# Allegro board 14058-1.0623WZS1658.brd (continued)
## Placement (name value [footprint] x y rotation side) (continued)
C442  SC1U10V2KX-1DLGP  [C402H22]  74.75 116.37 180 bottom
C443  SC4D7U6D3V3KX-DLGP  [C603H36]  91 117.59 180 bottom
C444  SCD1U16V2KX-3DLGP  [C402H22]  77.69 119.72 270 bottom
C445  SC1U10V2KX-1DLGP  [C402H22]  77.41 117.56 0 bottom
C446  SC4D7U6D3V3KX-DLGP  [C603H36]  84.57 114.01 180 bottom
C447  SC1KP50V2KX-1DLGP  [C402H22]  96.59 88.25 180 bottom
C448  SC1U10V2KX-1DLGP  [C402H22]  87.65 115.76 270 bottom
C449  SC22U6D3V5MX-2DLGP  [C805H54]  67.91 126.91 270 top
C452  SC22U6D3V5MX-2DLGP  [C805H54]  62.43 125.46 180 top
C453  SC4D7U6D3V3KX-DLGP  [C603H36]  80.87 110.51 90 bottom
C454  SC4D7U6D3V3KX-DLGP  [C603H36]  83.3 109.19 270 bottom
C455  SCD1U16V2KX-3DLGP  [C402H22]  75.25 114.95 90 bottom
C456  SC1U25V3KX-1-DLGP  [C603H36]  64.51 128.03 270 top
C458  SC4D7U6D3V3KX-DLGP  [C603H36]  78.78 106.36 270 bottom
C459  SC1U10V2KX-1DLGP  [C402H22]  81.1 106.54 270 bottom
C460  SC47U6D3V5MX-1DL-GP  [C805H54]  77.74 111.49 90 bottom
C461  SC4D7U6D3V3KX-DLGP  [C603H36]  84.12 107.33 90 bottom
C463  SCD1U16V2KX-3DLGP  [C402H22]  90.87 112.61 0 bottom
C464  SC4D7U6D3V3KX-DLGP  [C603H36]  81.45 107.56 90 bottom
C465  SCD1U16V2KX-3DLGP  [C402H22]  73.86 111.42 90 bottom
C466  SC4D7U6D3V3KX-DLGP  [C603H36]  86.26 109.65 90 bottom
C467  SC22U6D3V3MX-1-DL-GP  [C603H40]  92.02 112.99 0 bottom
C468  SC4D7U6D3V3KX-DLGP  [C603H36]  93.29 112.99 180 bottom
C469  SCD1U16V2KX-3DLGP  [C402H22]  89.86 112.61 0 bottom
C471  SC22U6D3V5MX-2DLGP  [C805H54]  77.72 113.52 90 bottom
C472  SC4D7U6D3V3KX-DLGP  [C603H36]  87.22 113.55 90 bottom
C473  SC4D7U6D3V3KX-DLGP  [C603H36]  87.98 112.36 90 bottom
C475  SCD1U16V2KX-3DLGP  [C402H22]  96.59 88.51 0 top
C476  SC4D7U6D3V3KX-DLGP  [C603H36]  72.26 113.07 0 bottom
C477  SC10U25V5KX-DL-GP  [C805H58]  64.59 125.46 180 top
C479  SC4D7U6D3V3KX-DLGP  [C603H36]  85.26 116.17 270 bottom
C481  SC4D7U6D3V3KX-DLGP  [C603H36]  88 114.72 90 bottom
C482  SC4D7U6D3V3KX-DLGP  [C603H36]  77.58 109.47 270 bottom
C484  SCD1U16V2KX-3DLGP  [C402H22]  90.11 110.07 0 bottom
C486  SC1U10V2KX-1DLGP  [C402H22]  78.19 107.72 90 bottom
C487  SC4D7U6D3V3KX-DLGP  [C603H36]  80.89 114.4 90 bottom
C488  SC4D7U6D3V3KX-DLGP  [C603H36]  83.57 111.34 270 bottom
C489  SC10U10V5KX-2DLGP  [C805H50]  27.5 125.54 180 top
C490  SC1U25V3KX-1-DLGP  [C603H36]  25.8 125.74 180 top
C491  SC10U6D3V3MX-DL-GP  [C603H36]  24.5 125.77 180 top
C492  SC4D7U6D3V3KX-DLGP  [C603H36]  87.78 107.31 180 bottom
C494  SCD01U25V2KX-3DLGP  [C402H22]  14.04 79.56 90 bottom
C495  SCD01U25V2KX-3DLGP  [C402H22]  14.04 78.55 90 bottom
C496  SCD01U25V2KX-3DLGP  [C402H22]  14.04 74.54 90 bottom
C497  SCD01U25V2KX-3DLGP  [C402H22]  14.04 73.62 90 bottom
C498  SCD01U25V2KX-3DLGP  [C402H22]  14.93 97.4 90 bottom
C499  SCD01U25V2KX-3DLGP  [C402H22]  14.93 96.38 90 bottom
C500  SCD01U25V2KX-3DLGP  [C402H22]  14.93 93.84 90 bottom
C501  SCD01U25V2KX-3DLGP  [C402H22]  14.93 92.82 90 bottom
C502  SCD1U16V2KX-3DLGP  [C402H22]  75.66 106.17 0 bottom
C503  SCD1U16V2KX-3DLGP  [C402H22]  79.09 105.32 90 bottom
C504  SC1U10V2KX-1DLGP  [C402H22]  48.58 101.59 180 bottom
C505  SC1U10V2KX-1DLGP  [C402H22]  48.58 101.59 0 top
C506  SCD1U16V2KX-3DLGP  [C402H22]  91.89 84.26 0 top
C511  SC15P50V2JN-DL-GP  [C402H22]  91.2 96.13 180 top
C512  SCD1U16V2KX-3DLGP  [C402H22]  146.88 234.56 90 top
C513  SC2D2U10V3KX-1DLGP-U  [C603H36]  147.14 233.41 90 top
C514  SCD1U16V2KX-3DLGP  [C402H22]  136.36 228.98 90 top
C515  SC2D2U10V3KX-1DLGP-U  [C603H36]  139.39 226.55 0 top
C516  SC10U6D3V3MX-DL-GP  [C603H36]  138.12 226.55 0 top
C517  SC10U6D3V3MX-DL-GP  [C603H36]  136.85 226.55 0 top
C518  SC1U10V2KX-1DLGP  [C402H22]  142.94 235.83 180 top
C519  SC1U10V2KX-1DLGP  [C402H22]  148.79 242.43 270 top
C520  SC10U10V5KX-2DLGP  [C805H50]  15.44 133.08 270 bottom
C522  SC10P50V2JN-4DLGP  [C402H22]  16.96 132.45 0 top
C523  SC10P50V2JN-4DLGP  [C402H22]  16.96 134.61 180 top
C524  SCD1U16V2KX-3DLGP  [C402H22]  23.44 18.02 180 top
C526  SCD1U16V2KX-3DLGP  [C402H22]  21.66 15.99 0 top
C528  SCD1U16V2KX-3DLGP  [C402H22]  23.44 20.05 180 top
C836  SCD1U16V2KX-3DLGP  [C402H22]  95.7 117.46 90 top
C837  SC22U6D3V5MX-2DLGP  [C805H54]  104.08 119.75 180 top
C1935  SCD1U16V2KX-3DLGP  [C402H22]  152.19 80.38 0 bottom
C3366  SCD1U16V2KX-3DLGP  [C402H22]  166.06 42.15 270 bottom
C3367  SC10U10V5KX-2DLGP  [C805H50]  141.29 45.07 0 top
C3453  SCD1U16V2KX-3DLGP  [C402H22]  91.26 27.67 180 top
C3454  SCD1U16V2KX-3DLGP  [C402H22]  60.27 21.83 0 bottom
C3457  SCD01U50V2KX-1DLGP  [C402H22]  10.48 16.88 90 top
C6702  SCD1U16V2KX-3DLGP  [C402H22]  36.39 115.56 0 top
C6704  SCD01U25V2KX-3LLGP  [C402H22]  62.05 110.78 0 top
C6705  SCD1U16V2KX-3DLGP  [C402H22]  86.76 107.35 0 bottom
C6706  SC4D7U6D3V3KX-DLGP  [C603H36]  80.89 112.46 90 bottom
C6707  SC4D7U6D3V3KX-DLGP  [C603H36]  70.68 117.84 90 bottom
C6708  SCD1U16V2KX-3DLGP  [C402H22]  91 110.07 0 bottom
C6709  SCD1U16V2KX-3-LL-GP  [C402H22]  87.14 117.56 180 bottom
C6710  SC22U6D3V3MX-1-DL-GP  [C603H40]  92.14 110.2 0 bottom
C6711  SC1U10V2KX-1DLGP  [C402H22]  51.63 97.12 0 top
C6712  SCD1U16V2KX-3DLGP  [C402H22]  53.03 97.65 90 top
C6713  SC1U10V2KX-1DLGP  [C402H22]  76.52 93.51 0 bottom
C6714  SCD1U16V2KX-3DLGP  [C402H22]  77.36 92.92 180 top
C6723  SC1U25V3KX-1-DLGP  [C603H36]  81.48 105.52 270 bottom
C6724  SC1U25V3KX-1-DLGP  [C603H36]  89.86 107.17 270 bottom
C6725  SC1U25V3KX-1-DLGP  [C603H36]  74.75 108.83 270 bottom
C7503  SCD1U10V2KX-4DLGP  [C402H22]  49.47 97.01 270 top
C7504  SCD1U10V2KX-4DLGP  [C402H22]  72.84 77.3 0 top
C7505  SCD1U16V2KX-3DLGP  [C402H22]  72.84 77.3 180 bottom
C7506  SCD1U10V2KX-4DLGP  [C402H22]  49.47 96 270 top
C7507  SCD1U16V2KX-3DLGP  [C402H22]  49.47 96 90 bottom
C7508  SCD1U16V2KX-3DLGP  [C402H22]  49.47 94.86 270 top
C7511  SCD1U10V2KX-4DLGP  [C402H22]  49.47 94.86 90 bottom
C7512  SCD1U16V2KX-3DLGP  [C402H22]  54.93 124.7 180 top
C7516  SCD1U16V2KX-3DLGP  [C402H22]  54.93 124.7 0 bottom
C7521  SCD1U10V2KX-4DLGP  [C402H22]  48.96 115.94 270 top
C7522  SCD1U16V2KX-3DLGP  [C402H22]  48.96 114.92 270 top
C9504  SCD1U16V2KX-3DLGP  [C402H22]  36.65 47.87 90 bottom
C9516  SC4D7U6D3V3KX-DLGP  [C603H36]  33.34 42.53 270 bottom
C9518  SCD1U16V2KX-3DLGP  [C402H22]  30.04 48.37 0 bottom
C9520  SC18P50V2JN-1DLGP  [C402H22]  45.17 23.34 90 top
C9522  SC18P50V2JN-1DLGP  [C402H22]  43.14 23.34 270 top
C11358  SC1U10V2KX-1DLGP  [C402H22]  176.41 48.75 180 top
C11359  SCD1U16V2KX-3DLGP  [C402H22]  177.36 48.75 180 top
C11833  SC1U10V2KX-1DLGP  [C402H22]  148.41 81.32 0 bottom
C11834  SC1U10V2KX-1DLGP  [C402H22]  138.75 75.93 270 bottom
C11835  SC1U10V2KX-1DLGP  [C402H22]  153.87 80 0 bottom
C11836  SC1U10V2KX-1DLGP  [C402H22]  142.69 88.76 0 bottom
C11837  SC1U10V2KX-1DLGP  [C402H22]  127.78 93.84 270 top
C11838  SC1U10V2KX-1DLGP  [C402H22]  167.84 58.03 270 top
C11839  SC1U10V2KX-1DLGP  [C402H22]  135.45 63.36 180 top
C11888  SC22U6D3V5MX-2DLGP  [C805H54]  129.1 96 270 top
C11892  SC47P50V2JN-3GP  [C402H22]  140.82 61.29 0 top
C11895  SCD22U10V2KX-2-GP  [C402H22]  77 132.18 0 top
C11898  SCD22U10V2KX-2-GP  [C402H22]  75.48 130.03 0 top
C11900  SCD22U10V2KX-2-GP  [C402H22]  78.53 130.01 0 top
C11902  SCD22U10V2KX-2-GP  [C402H22]  79.92 132.17 0 top
C11904  SCD22U10V2KX-2-GP  [C402H22]  81.19 130.01 0 top
C11905  SCD22U10V2KX-2-GP  [C402H22]  82.46 132.17 0 top
C11907  SCD22U10V2KX-2-GP  [C402H22]  84.62 130.01 0 top
C11908  SCD22U10V2KX-2-GP  [C402H22]  85 132.17 0 top
C12052  SCD01U16V2KX-3DLGP  [C402H22]  154.63 57.39 90 top
C12055  SCD1U16V2KX-3DLGP  [C402H22]  19.88 161.02 90 top
C12056  SC10U10V5KX-2DLGP  [C805H50]  38.68 148.45 90 top
C12057  SCD1U16V2KX-3DLGP  [C402H22]  39.31 149.97 90 top
C12058  SCD1U50V3KX-DL-GP  [C603H35]  36.82 150.1 90 top
C12059  SCD1U50V3KX-DL-GP  [C603H35]  36.82 151.32 270 top
C12060  SCD1U50V3KX-DL-GP  [C603H35]  40.21 154.58 0 top
C12061  SCD1U16V2KX-3DLGP  [C402H22]  152.6 72 90 bottom
C12063  SCD1U16V2KX-3DLGP  [C402H22]  99.89 54.85 180 top
C12064  SCD1U16V2KX-3DLGP  [C402H22]  104.72 54.22 0 bottom
C12065  SC2200P50V2KX-2DLGP  [C402H22]  98.88 55.87 0 bottom
C12098  SC1U100V6KX-LL-GP  [C1206H71]  25.98 6.06 180 bottom
C12100  SC1U100V6KX-LL-GP  [C1206H71]  28.28 6.05 180 bottom
C12101  SCD1U25V3ZY-1-LL-GP  [C603H36]  5.58 14.49 180 top
C12103  SC1U100V6KX-LL-GP  [C1206H71]  32.86 6.06 180 bottom
C12107  SC1U100V6KX-LL-GP  [C1206H71]  30.58 6.06 180 bottom
C12108  SC1U100V6KX-LL-GP  [C1206H71]  35.15 6.06 180 bottom
C12113  SC4D7U10V3KX-DL-GP  [C603H36]  20.26 48.75 180 bottom
C12114  SCD01U25V2KX-3DLGP  [C402H22]  17.21 52.18 90 bottom
C12118  SCD1U16V2KX-3DLGP  [C402H22]  64.52 32.97 180 top
C12119  SCD1U16V2KX-3DLGP  [C402H22]  63.5 32.96 180 top
C12120  SC1U10V2KX-1DLGP  [C402H22]  53.66 21.45 0 bottom
C12121  SC2D2U10V3KX-1DLGP-U  [C603H36]  66.24 26.4 90 top
C12122  SC1U10V2KX-1DLGP  [C402H22]  59.76 14.08 180 top
C12123  SC1U10V2KX-1DLGP  [C402H22]  55.95 16.88 270 top
C12125  SC47P50V2JN-5DLGP  [C402H22]  37.41 232.27 90 top
C12126  SC47P50V3JN-DLGP  [C603H35]  110.56 71.74 270 top
C12127  SC10U10V5KX-2DLGP  [C805H50]  185.36 52.44 90 top
C12128  SCD1U16V2KX-3DLGP  [C402H22]  64.08 21.83 0 bottom
C12131  SC10U10V5KX-2DLGP  [C805H50]  185.74 148.58 90 bottom
C12138  SCD22U10V2KX-2-GP  [C402H22]  76.37 130.03 0 top
C12139  SCD22U10V2KX-2-GP  [C402H22]  77.89 132.18 0 top
C12140  SCD22U10V2KX-2-GP  [C402H22]  79.41 130.01 0 top
C12141  SCD22U10V2KX-2-GP  [C402H22]  80.81 132.17 0 top
C12142  SCD22U10V2KX-2-GP  [C402H22]  82.08 130.01 0 top
C12143  SCD22U10V2KX-2-GP  [C402H22]  83.35 132.17 0 top
C12144  SCD22U10V2KX-2-GP  [C402H22]  83.73 130.01 0 top
C12145  SCD22U10V2KX-2-GP  [C402H22]  85.89 132.17 0 top
C12148  SCD1U16V2KX-3DLGP  [C402H22]  145.36 175.12 180 bottom
C12149  SC1U10V2KX-1DLGP  [C402H22]  147.26 123.43 180 top
C12150  SC1U10V2KX-1DLGP  [C402H22]  149.93 120.89 0 top
C12151  SC2D2U6D3V2MX-DL-GP  [C402H22]  116.25 69.94 270 top
C12152  SC1U10V2KX-1DLGP  [C402H22]  114.29 68.97 90 top
C12153  SC10U6D3V3MX-DL-GP  [C603H36]  182.19 51.93 270 top
C12154  SCD1U16V2KX-3DLGP  [C402H22]  57.22 31.86 0 bottom
C12155  SCD1U16V2KX-3DLGP  [C402H22]  187.27 146.04 270 bottom
C12156  SC1U10V2KX-1DLGP  [C402H22]  194.52 137.64 0 bottom
C12157  SC4D7U6D3V3KX-DLGP  [C603H36]  190.44 149.34 0 bottom
C12158  SCD1U16V2KX-3DLGP  [C402H22]  191.55 149.17 180 bottom
C12159  SC1U10V2KX-1DLGP  [C402H22]  196.46 144.39 90 bottom
C12160  SCD1U16V2KX-3DLGP  [C402H22]  188.03 148.58 180 bottom
C12161  SC1U10V2KX-1DLGP  [C402H22]  189.01 148.58 180 bottom
C12162  SCD1U16V2KX-3DLGP  [C402H22]  191.46 135.09 270 bottom
C12163  SC4D7U6D3V3KX-DLGP  [C603H36]  191.53 134.07 90 bottom
C12164  SC1KP50V2KX-1DLGP  [C402H22]  142.06 94.47 180 top
C12165  SC1U10V2KX-1DLGP  [C402H22]  24.96 253.35 90 bottom
C12166  SCD1U16V2KX-3DLGP  [C402H22]  24.83 251.76 180 bottom
C12167  SCD1U16V2KX-3DLGP  [C402H22]  173.93 205.47 270 bottom
C12168  SCD1U16V2KX-3DLGP  [C402H22]  161.36 206.74 180 bottom
C12169  SC4D7U6D3V3KX-DLGP  [C603H36]  27.12 32.75 0 bottom
C12170  SCD1U16V2KX-3DLGP  [C402H22]  63.06 9.51 0 top
C12171  SCD1U50V3KX-DL-GP  [C603H35]  41.22 38.34 270 bottom
C12172  SCD1U16V2KX-3DLGP  [C402H22]  29.66 39.36 90 bottom
C12174  SC10U10V5KX-2DLGP  [C805H50]  41.98 27.16 270 bottom
C12175  SCD1U16V2KX-3DLGP  [C402H22]  40.46 19.47 270 top
C12176  SCD1U16V2KX-3DLGP  [C402H22]  40.46 18.58 270 top
C12179  SCD1U16V2KX-3DLGP  [C402H22]  47.19 32.63 270 top
C12180  SCD1U16V2KX-3DLGP  [C402H22]  47.19 33.51 270 top
C12181  SCD1U16V2KX-3DLGP  [C402H22]  47.19 34.4 270 top
C12182  SCD1U16V2KX-3DLGP  [C402H22]  47.19 35.29 270 top
C12183  SCD1U16V2KX-3DLGP  [C402H22]  38.04 27.55 270 bottom
C12184  SCD1U16V2KX-3DLGP  [C402H22]  31.44 30.21 90 bottom
C12185  SC10U6D3V3MX-DL-GP  [C603H36]  47.44 26.78 0 top
C12186  SCD1U16V2KX-3DLGP  [C402H22]  43.38 37.96 0 bottom
C12187  SCD1U16V2KX-3DLGP  [C402H22]  46.3 27.42 0 top
C12188  SCD1U16V2KX-3DLGP  [C402H22]  46.93 40.25 180 top
C12189  SC4D7U6D3V3KX-DLGP  [C603H36]  48.08 40.63 180 top
C12190  SC1U25V3KX-1-DLGP  [C603H36]  44.06 51.6 180 top
C12191  SCD1U16V2KX-3DLGP  [C402H22]  37.66 48.75 270 bottom
C12192  SC1U10V2KX-1DLGP  [C402H22]  42.46 51.73 270 top
C12193  SC1U10V2KX-1DLGP  [C402H22]  40.1 51.29 180 top
C12194  SCD1U16V2KX-3DLGP  [C402H22]  31.06 48.37 0 bottom
C12195  SCD1U16V2KX-3DLGP  [C402H22]  32.07 48.37 0 bottom
C12196  SCD1U16V2KX-3DLGP  [C402H22]  29.41 43.17 0 bottom
C12197  SCD1U16V2KX-3DLGP  [C402H22]  29.03 37.83 0 bottom
C12199  SCD1U16V2KX-3DLGP  [C402H22]  151.45 33.9 270 bottom
C12200  SCD1U16V2KX-3DLGP  [C402H22]  167.2 46.47 90 top
C12201  SCD01U50V2KX-1DLGP  [C402H22]  153.71 51.68 180 top
C12202  SCD1U16V2KX-3DLGP  [C402H22]  155.01 43.29 270 top
C12203  SCD01U50V2KX-1DLGP  [C402H22]  155.01 42.4 270 top
C12204  SCD1U16V2KX-3DLGP  [C402H22]  166.06 43.04 270 bottom
C12205  SCD01U50V2KX-1DLGP  [C402H22]  149.04 49.52 180 top
C12206  SCD1U16V2KX-3DLGP  [C402H22]  165.68 47.48 0 bottom
C12207  SCD01U50V2KX-1DLGP  [C402H22]  155.52 46.6 180 bottom
C12208  SCD1U10V2KX-4DLGP  [C402H22]  159.45 51.68 0 top
C12209  SCD1U10V2KX-4DLGP  [C402H22]  158.57 51.68 0 top
C12210  SCD1U10V2KX-4DLGP  [C402H22]  163.26 51.68 0 top
C12211  SCD1U10V2KX-4DLGP  [C402H22]  162.38 51.68 0 top
C12212  SCD1U10V2KX-4DLGP  [C402H22]  167.07 51.68 0 top
C12213  SCD1U10V2KX-4DLGP  [C402H22]  166.19 51.68 0 top
C12214  SCD1U10V2KX-4DLGP  [C402H22]  155.52 51.68 0 top
C12215  SCD1U10V2KX-4DLGP  [C402H22]  154.63 51.68 0 top
C12216  SCD1U16V2ZY-2DLGP  [C402H22]  142.31 15.99 180 top
C12217  SCD1U16V2ZY-2DLGP  [C402H22]  155.16 20.94 0 top
C12218  SC33P50V2JN-3DLGP  [C402H22]  148.15 23.74 0 top
C12219  SC33P50V2JN-3DLGP  [C402H22]  148.15 25.77 180 top
C12220  SCD1U16V2KX-3DLGP  [C402H22]  25.22 53.71 270 bottom
C12221  SCD1U16V2KX-3DLGP  [C402H22]  25.22 54.72 270 bottom
C12222  SCD1U16V2KX-3DLGP  [C402H22]  24.96 52.82 270 bottom
C12223  SCD1U16V2KX-3DLGP  [C402H22]  25.49 54.72 90 top
C12224  SC10U25V5KX-DL-GP  [C805H58]  7.33 6.13 270 top
C12225  SC10U25V5KX-DL-GP  [C805H58]  7.33 8.37 270 top
C12226  SCD1U16V2KX-3DLGP  [C402H22]  10.1 17.94 90 top
C12227  SCD01U50V2KX-1DLGP  [C402H22]  8.2 13.96 270 top
C12228  SC1KP50V2KX-1DLGP  [C402H22]  13.28 19.32 270 bottom
C12229  SC27P50V2JN-2DLGP  [C402H22]  9.97 19.06 270 bottom
C12230  SCD1U16V2KX-3DLGP  [C402H22]  9.97 19.95 270 bottom
C12231  SCD1U25V2KX-1-DL-GP  [C402H22]  14.67 19.67 180 top
C12232  SCD1U25V2KX-1-DL-GP  [C402H22]  15.56 19.67 180 top
C12233  SCD1U25V2KX-1-DL-GP  [C402H22]  16.45 19.67 0 bottom
C12234  SCD47U25V3KX-1-DL-GP  [C603H36]  18.23 16.12 270 top
C12235  SC100P50V2JN-3DLGP  [C402H22]  14.17 11.29 90 bottom
C12236  SC4D7U10V3KX-DL-GP  [C603H36]  9.34 13.83 270 bottom
C12237  SC1U10V2KX-1DLGP  [C402H22]  144.6 235.32 270 top
C12238  SCD1U16V2KX-3DLGP  [C402H22]  23.44 21.96 0 top
C12239  SCD1U16V2KX-3DLGP  [C402H22]  30.68 114.03 180 top
C12240  SC10U6D3V3MX-DL-GP  [C603H36]  38.3 116.19 90 top
C12241  SCD1U16V2KX-3DLGP  [C402H22]  48.36 127.26 90 top
C12242  SCD1U16V2KX-3DLGP  [C402H22]  30.68 124.07 270 top
C12243  SCD1U16V2KX-3DLGP  [C402H22]  42.49 125.59 270 top
C12244  SC10U6D3V3MX-DL-GP  [C603H36]  28.77 48.37 0 bottom
C12245  SC10U10V5KX-2DLGP  [C805H50]  31.31 36.56 180 bottom
C12246  SC10U10V5KX-2DLGP  [C805H50]  31.44 32.63 180 bottom
C12264  SCD22U10V2KX-2-GP  [C402H22]  88.43 129.14 180 bottom
C12265  SCD22U10V2KX-2-GP  [C402H22]  87.54 129.14 180 bottom
C12266  SCD22U10V2KX-2-GP  [C402H22]  86.66 127.99 180 bottom
C12267  SCD22U10V2KX-2-GP  [C402H22]  85.77 127.99 180 bottom
C12268  SCD22U10V2KX-2-GP  [C402H22]  82.85 131.68 180 bottom
C12269  SCD22U10V2KX-2-GP  [C402H22]  83.73 131.68 180 bottom
C12270  SCD22U10V2KX-2-GP  [C402H22]  82.46 129.52 180 bottom
C12271  SCD22U10V2KX-2-GP  [C402H22]  81.58 129.52 180 bottom
C12272  SCD22U10V2KX-2-GP  [C402H22]  80.56 130.79 180 bottom
C12273  SCD22U10V2KX-2-GP  [C402H22]  79.67 130.79 180 bottom
C12274  SCD22U10V2KX-2-GP  [C402H22]  79.04 127.99 180 bottom
C12275  SCD22U10V2KX-2-GP  [C402H22]  78.15 127.99 180 bottom
C12276  SCD22U10V2KX-2-GP  [C402H22]  77.51 130.76 180 bottom
C12277  SCD22U10V2KX-2-GP  [C402H22]  76.62 130.76 180 bottom
C12278  SCD22U10V2KX-2-GP  [C402H22]  74.44 128.53 180 bottom
C12279  SCD22U10V2KX-2-GP  [C402H22]  75.33 128.53 180 bottom
C12314  SCD1U50V3KX-DL-GP  [C603H35]  114.24 91.55 90 top
C12324  SCD1U50V3KX-DL-GP  [C603H35]  16.71 171.18 90 top
C12325  SCD1U50V3KX-DL-GP  [C603H35]  9.85 167.63 0 top
C12326  SC10U10V5KX-2DLGP  [C805H50]  12.52 168.39 90 top
C12327  SCD1U16V2KX-3DLGP  [C402H22]  15.82 168.9 90 top
C12328  SCD01U50V2ZY-1GP  [C402H22]  83.64 27.16 90 top
C12329  SC10U10V5KX-2DLGP  [C805H50]  115.13 38.09 180 top
C12330  SC10U10V5KX-2DLGP  [C805H50]  113.1 38.09 180 top
C12331  SC1U10V2KX-1DLGP  [C402H22]  180.79 42.79 90 top
C12332  SC1U10V2KX-1DLGP  [C402H22]  177.54 41.55 270 top
C12333  SC100P3KV8JN-2-GP  [C1808H56]  85.21 17.18 0 bottom
C12334  SCD01U25V2KX-3DLGP  [C402H22]  82.24 19.49 180 top
C12336  SCD1U25V3KX-DLGP  [C603H36]  56.63 30.31 90 bottom
C12337  SCD1U16V2KX-3DLGP  [C402H22]  47.19 36.18 270 top
C12338  SCD1U16V2KX-3DLGP  [C402H22]  47.19 37.07 270 top
C12339  SCD1U16V2KX-3DLGP  [C402H22]  47.19 37.96 270 top
C12340  SCD1U16V2KX-3DLGP  [C402H22]  47.19 38.85 270 top
C12341  SCD1U16V2KX-3DLGP  [C402H22]  29.28 132.19 270 top
C12376  SC10U6D3V3MX-DL-GP  [C603H36]  71.9 123.2 270 bottom
C12377  SC4D7U6D3V3KX-DLGP  [C603H36]  86.26 110.84 90 bottom
C12378  SCD1U16V2KX-3DLGP  [C402H22]  84.57 105.88 90 bottom
C12379  SCD1U16V2KX-3DLGP  [C402H22]  85.9 107.35 0 bottom
C12380  SCD1U16V2KX-3DLGP  [C402H22]  81.35 103.87 180 bottom
C12381  SC1U10V2KX-1DLGP  [C402H22]  82.7 113.93 0 bottom
C12382  SCD01U50V2KX-1DLGP  [C402H22]  91.26 120.89 0 bottom
C12383  SC15P50V2JN-DL-GP  [C402H22]  91.2 94.22 0 top
C12384  SC100P50V2JN-3DLGP  [C402H22]  99.26 115.43 0 top
C12385  SC1U10V2KX-1DLGP  [C402H22]  91.31 83.86 270 bottom
C12386  SCD1U16V2KX-3DLGP  [C402H22]  91.76 88.43 180 top
C12387  SC1U10V2KX-1DLGP  [C402H22]  71.44 99.81 180 bottom
C12388  SCD1U16V2KX-3DLGP  [C402H22]  70.17 78.6 0 top
C12389  SCD1U16V2KX-3DLGP  [C402H22]  83.51 78.98 180 bottom
C12390  SC1U10V2KX-1DLGP  [C402H22]  84.65 78.95 0 top
C12391  SC1U10V2KX-1DLGP  [C402H22]  53.79 124.7 180 top
C12392  SC1U10V2KX-1DLGP  [C402H22]  61.16 110.86 180 bottom
C12393  SC1U10V2KX-1DLGP  [C402H22]  63.7 110.73 270 top
C12394  SCD1U16V2KX-3DLGP  [C402H22]  57.47 124.19 90 top
C12395  SCD1U16V2KX-3DLGP  [C402H22]  57.47 124.19 270 bottom
C12397  SCD1U16V2KX-3DLGP  [C402H22]  59 124.7 180 top
C12400  SC1U10V2KX-1DLGP  [C402H22]  62.43 85.33 0 bottom
C12401  SC1U10V2KX-1DLGP  [C402H22]  91.26 88.76 270 bottom
C12403  SC1U10V2KX-1DLGP  [C402H22]  91.26 87.87 270 bottom
C12405  SC1U10V2KX-1DLGP  [C402H22]  91.31 84.77 270 bottom
C12406  SC1U10V2KX-1DLGP  [C402H22]  91.31 85.79 270 bottom
C12407  SC1U10V2KX-1DLGP  [C402H22]  84.65 78.95 180 bottom
C12408  SC1U10V2KX-1DLGP  [C402H22]  86.18 79.46 270 bottom
C12409  SCD1U16V2KX-3DLGP  [C402H22]  70.94 106.41 270 bottom
C12413  SCD1U16V2KX-3DLGP  [C402H22]  76.52 95.49 180 bottom
C12414  SCD1U16V2KX-3DLGP  [C402H22]  77.03 92.06 270 bottom
C12415  SCD1U16V2KX-3DLGP  [C402H22]  71.07 108.79 270 bottom
C12416  SC1U10V2KX-1DLGP  [C402H22]  70.94 107.3 270 bottom
C12417  SC1U10V2KX-1DLGP  [C402H22]  48.58 99.43 0 top
C12418  SCD1U16V2KX-3DLGP  [C402H22]  48.58 99.43 180 bottom
C12419  SC1U10V2KX-1DLGP  [C402H22]  51.43 93.23 0 top
C12422  SCD1U16V2KX-3DLGP  [C402H22]  49.22 92.19 270 bottom
C12423  SC1U10V2KX-1DLGP  [C402H22]  48.96 115.94 90 bottom
C12424  SC1U10V2KX-1DLGP  [C402H22]  48.96 114.92 90 bottom
C12425  SCD1U16V2KX-3DLGP  [C402H22]  60.9 124.83 0 bottom
C12426  SC1U10V2KX-1DLGP  [C402H22]  60.01 124.7 180 top
C12427  SC1U10V2KX-1DLGP  [C402H22]  60.01 124.83 0 bottom
C12429  SC1U10V2KX-1DLGP  [C402H22]  56.36 97.62 270 bottom
C12431  SC1U10V2KX-1DLGP  [C402H22]  63.7 110.73 90 bottom
C12433  SCD1U16V2KX-3DLGP  [C402H22]  62.05 110.86 180 bottom
C12434  SC10U6D3V3MX-DL-GP  [C603H36]  50.56 125.08 180 top
C12435  SC10U6D3V3MX-DL-GP  [C603H36]  50.62 125.08 0 bottom
C12436  SC10U6D3V3MX-DL-GP  [C603H36]  48.58 117.21 90 bottom
C12437  SC10U6D3V3MX-DL-GP  [C603H36]  48.58 117.21 270 top
C12438  SC10U6D3V3MX-DL-GP  [C603H36]  66.24 78.22 0 top
C12439  SC10U6D3V3MX-DL-GP  [C603H36]  66.24 78.22 180 bottom
C12440  SC10U6D3V3MX-DL-GP  [C603H36]  82.37 78.6 180 bottom
C12441  SC10U6D3V3MX-DL-GP  [C603H36]  82.37 78.6 0 top
C12442  SC470P50V2KX-3DLGP  [C402H22]  19.75 135.37 0 top
C12443  SCD01U16V2KX-3DLGP  [C402H22]  167.84 42.02 0 top
C12444  SC22U6D3V5MX-2DLGP  [C805H54]  73.6 195.13 180 bottom
C12445  SC22U6D3V5MX-2DLGP  [C805H54]  71.32 195.13 180 bottom
C12446  SCD1U16V2KX-3DLGP  [C402H22]  94.58 51.17 270 bottom
CN3  ACES-CON4-37-GP  [88459-047N]  174.69 92.82 90 top
CONVT1  CLX-CONN20G-GP  [CI1410M1VL0-NH]  28.08 7.5 180 top
CPU1  SKYLAKE-1  [SKTBGA1151Z753620H369]  75.04 187.44 90 top
D2  BAS40C-2-GP  [SOT-23-9H44]  126.05 100.95 90 top
D3  RB551V30-GP  [SOD323AKH38]  125.04 96.38 0 top
D4  1SS355-4-GP  [SOD323AKH38]  7.31 170.04 180 bottom
D5  AZ2015-01H-GP  [SOD523AKH28]  177.23 70.34 0 top
D9  IP4223CZ6-1-GP  [SOT-6H44]  186.51 109.21 90 top
D10  IP4223CZ6-1-GP  [SOT-6H44]  127.32 32.75 180 top
D11  IP4223CZ6-1-GP  [SOT-6H44]  140.66 31.48 180 top
D12  P6SMB27A-1-GP  [DO214AAAK-1121H97]  84.14 24.37 270 top
D13  BAV99GP-GP  [SOT23-2D4-312H48]  51.12 32.12 90 top
D23  1SS355-4-GP  [SOD323AKH38]  168.09 43.29 180 bottom
D32  BX310F-R1-00000-GP  [D4724AKH44]  23.06 8.75 0 bottom
D5201  BAT54C-12-GP  [SOT-23-9H44]  157.7 20.36 0 top
D5202  BZX84-C6V8-GP  [SOT-23-9H44]  157.68 24.5 0 top
D5203  SP3010-04UTG-GP  [SLP2510P8-1H22]  160.85 13.96 90 top
D5204  SP3010-04UTG-GP  [SLP2510P8-1H22]  160.98 8.5 270 top
D5205  1SS355GP-GP  [SOD323AKH40]  99.38 120.51 180 top
D5206  1SS355GP-GP  [SOD323AKH40]  34.11 104.25 180 top
D5209  1SS355GP-GP  [SOD323AKH40]  105.73 133.84 270 top
D5210  AZ5725-01FDR7G-GP  [SOD882-10D6-1H20]  28.64 16.88 90 bottom
D5211  AZ5725-01FDR7G-GP  [SOD882-10D6-1H20]  25.47 20.05 270 bottom
D5212  AZ5725-01FDR7G-GP  [SOD882-10D6-1H20]  25.47 21.07 270 bottom
D5213  AZ5725-01FDR7G-GP  [SOD882-10D6-1H20]  27.88 20.05 90 bottom
D5214  AZ5725-01FDR7G-GP  [SOD882-10D6-1H20]  24.71 18.15 270 bottom
DB1  PIN-CON2-S-GP  [210-41-02GB01]  146.37 55.1 0 top
DB2  PIN-CON2-S-GP  [210-41-02GB01]  152.47 55.1 0 top
DCIN1  DC-JACK345-GP  [2DC3115-000111F]  73.25 24.73 270 top
DIMM1  DDR3-204P-252-GP-U  [DAN06-K4406-0103-U]  149.35 167 90 top
DIMM2  DDR3-204P-278-GP  [DAN06-K4806-0103]  164.55 167 90 top
F6  POLYSW-1D5A6V-12-GP  [POLYSW-2114H30]  176.22 196.84 270 top
F7  POLYSW-1D5A6V-12-GP  [POLYSW-2114H30]  151.96 35.55 270 bottom
F12  POLYSW-1D5A6V-12-GP  [POLYSW-2114H30]  15.44 135.24 90 bottom
F14  POLYSW-2A6V-7-GP  [POLYSW-2114H30]  177.62 90.03 180 top
F16  FUSE-3A32V-26-GP  [FUSE-1608H22]  7.44 10.27 90 top
F17  POLYSW-2A6V-7-GP  [POLYSW-2114H30]  20.26 56.37 270 bottom
F18  POLYSW-2A6V-7-GP  [POLYSW-2114H30]  113.73 22.59 90 top
F19  POLYSW-2A6V-7-GP  [POLYSW-2114H30]  110.18 37.96 90 top
F20  POLYSW-1D5A6V-12-GP  [POLYSW-2114H30]  176.22 199.12 270 top
F21  POLYSW-2A6V-7-GP  [POLYSW-2114H30]  13.28 163.82 270 bottom
FANC3  FOX-CON4-30-GP  [HF1804H]  13.28 175 270 top
G1  COPPER-CLOSE-GP-U  [CON2C-U]  92.02 53.96 0 top
GPU1  N16S-GM-S-A2-GP  [BGA595M23H83]  81.08 110.92 180 top
H13  GEN8D5X8R5X4D5-8-F-A-GP  [GEN8D5X8R5X4D5-8-F-A]  6.53 146.06 270 top
H14  GEN8D5X8R5X4D5-8-F-A-GP  [GEN8D5X8R5X4D5-8-F-A]  60.01 43.02 180 top
H15  HOLE315R158-GP  [HOLE315R158]  49.36 231.27 180 top
H16  HOLE315R158-GP  [HOLE315R158]  101.36 231.23 180 top
H17  HOLE315R158-GP  [HOLE315R158]  49.3 143.27 180 top
H18  HOLE315R158-GP  [HOLE315R158]  101.3 143.23 180 top
H19  HOLE315R158-GP  [HOLE315R158]  65.78 134.01 180 top
H20  HOLE315R158-GP  [HOLE315R158]  101.08 82.39 180 top
H22  GEN315R178-8-F-A-3-GP  [GEN315R178-8-F-A-1]  185 19.2 180 top
H23  GEN315R138-8-F-A-2-S-GP  [GEN315R138-8-F-A-2-S]  192.49 63.65 180 top
H24  GEN8D5X8R5X4D5-8-F-A-GP  [GEN8D5X8R5X4D5-8-F-A]  184.93 224.22 270 top
H25  GEN315R138-8-F-A-1-GP  [GEN315R138-8-F-A-1]  45.71 265.47 180 top
HDD1  SKT-SATA7P-184-GP-U  [15-02070-5A61-A]  9.28 76 270 top
HDMI1  SKT-HDMI22-12-GP  [SKT-HDMI22-150077]  147.78 36.23 270 top
HDMI2  SKT-HDMI22-12-GP  [SKT-HDMI22-150077]  147.78 13.23 270 top
HS6  STF256R109H99-GP  [STF256R109H99]  158.53 238 0 top
L1  MHC1608S181NBP-GP  [L603H38]  91.51 47.48 270 top
L3  MCB1005S121FBP-GP  [L402H24]  169.79 53.4 0 top
L4  HCB1608KF-800T30-GP  [L603H38]  179.27 69.33 270 top
L5  MCB1005S121FBP-GP  [L402H24]  182.06 50.79 90 top
L6  MHC1608S221NBP-GP  [L603H38]  163.14 33.9 180 bottom
L7  HCB2012KF-601T20-GP  [L20125H42]  163.14 28.31 0 top
L8  HCB2012KF-601T20-GP  [L20125H42]  166.82 28.56 270 top
L10  HCB2012KF-601T20-GP  [L20125H42]  174.82 27.16 180 bottom
L11  HCB2012KF-601T20-GP  [L20125H42]  172.66 27.16 180 bottom
L12  MCB1005S121FBP-GP  [L402H24]  105.1 33.88 180 top
L13  MCB1005S121FBP-GP  [L402H24]  103.96 33.9 180 top
L17  FILTER-4P-123-GP  [L125100-4P-1H36]  185.62 95.74 180 top
L18  FILTER-4P-123-GP  [L125100-4P-1H36]  185.62 93.08 180 top
L19  FILTER-4P-123-GP  [L125100-4P-1H36]  184.35 116.57 180 top
L20  FILTER-4P-123-GP  [L125100-4P-1H36]  184.35 114.29 180 top
L21  BLM15BD102SN1D-GP  [L402H22]  54.43 24.88 0 bottom
L25  -  [0R0805-PAD]  151.96 37.71 270 bottom
L27  MHC1608S300QBP-GP  [L603H38]  70.33 127.93 0 top
L28  MHC1608S181NBP-GP  [L603H38]  94.81 111.21 0 bottom
L29  MHC1608S300QBP-GP  [L603H38]  93.41 110.2 180 bottom
L61  IND-33UH-85-GP  [L8080-6020H158]  14.29 9.51 90 top
L62  HCB2012KF-600T30-GP  [L20125H42]  17.09 55.61 0 bottom
L4102  FILTER-4P-123-GP  [L125100-4P-1H36]  16.15 80.76 90 bottom
L4103  FILTER-4P-123-GP  [L125100-4P-1H36]  16.15 75.93 90 bottom
L9502  MHC1608S181NBP-GP  [L603H38]  47.19 24.5 90 top
L9503  MHC1608S181NBP-GP  [L603H38]  31.31 39.86 0 bottom
L9504  MHC1608S181NBP-GP  [L603H38]  28.39 32.75 180 bottom
L9505  MHC1608S181NBP-GP  [L603H38]  32.58 39.86 0 bottom
L9523  MHC1608S181NBP-GP  [L603H38]  49.35 40.63 0 top
L9524  MCB1608S121IBP-GP  [L603H38]  74.59 125.51 90 bottom
LED2  LED-O-23-GP  [LED1608AKH30]  66.49 49.14 90 top
LOUT1  AUDIO-JK419-GP  [JAC331-0140A8B-9H]  96.93 36.86 90 top
LPC1  FOX-CONN14A-S1-GP  [HL5507F]  134.56 55.87 180 top
LVDS1  ACES-CON30-21-GP  [50524-0300N-001]  16.28 43 270 top
MEJ1  JOWLE-CON2-5-GP  [A2541WV0-1EX2PA-6T]  137.36 124.07 90 top
MEMCD1  SDCARD-19P-3-GP  [156-2131302600]  180.78 143.49 90 top
NGFF1  SKT-MINI67P-3-GP-U1  [2199230-7]  130.28 238 270 top
NOREF  -  [unnamed]  4.39 265.8 0 top
NOREF#2  *  [unnamed]  5.13 28.05 0 top
NOREF#3  *  [unnamed]  132.15 48.25 0 top
NOREF#4  -  [unnamed]  180.54 255.51 0 top
NOREF#5  -  [#2]  131.64 193.41 0 top
NOREF#6  -  [unnamed]  5.13 42.98 0 top
NOREF#7  -  [#2]  119.58 171.31 270 top
NOREF#8  -  [unnamed]  205.94 263.81 0 top
NOREF#9  *  [unnamed]  6.33 3.19 0 top
NOREF#10  -  [unnamed]  195.78 259.45 0 top
NOREF#11  *  [unnamed]  178.12 250.25 0 top
NOREF#12  *  [unnamed]  205.94 14.33 0 top
NOREF#13  -  [unnamed]  199.46 24.62 0 top
NOREF#14  *  [unnamed]  205.94 258.22 0 top
NOREF#15  *  [unnamed]  115.39 227.7 0 top
NOREF#16  -  [#2]  -13.52 -15 0 top
NOREF#17  *  [unnamed]  94.81 135.01 0 top
NOREF#18  -  [unnamed]  122.56 89.85 0 top
NOREF#19  *  [unnamed]  179.77 6.08 0 top
NOREF#20  -  [#2]  68.73 142.23 0 top
NOREF#21  -  [unnamed]  175.58 7.48 0 top
NOREF#22  -  [#2]  212 243.84 0 top
NOREF#23  *  [unnamed]  6.9 262.72 0 top
NOREF#24  *  [unnamed]  56.46 50.02 0 top
NOREF#25  *  [unnamed]  35.12 88.4 0 top
NOREF#26  -  [#2]  12.9 249.03 0 top
NOREF#27  -  [#2]  -13.52 -15 0 top
NOREF#28  -  [unnamed]  205.94 6.92 0 top
NOREF#29  -  [unnamed]  159.56 65.85 0 top
NOREF#30  -  [#2]  15.31 258.69 0 top
NOREF#31  *  [unnamed]  6.93 262.75 180 bottom
NOREF#32  *  [unnamed]  5.66 12.43 180 bottom
NOREF#33  *  [unnamed]  35.12 88.4 180 bottom
NOREF#34  *  [unnamed]  205.94 258.22 180 bottom
NOREF#35  *  [unnamed]  205.94 14.33 180 bottom
NOREF#36  *  [unnamed]  181.43 9 180 bottom
NOREF#37  *  [unnamed]  56.58 250.68 180 bottom
NOREF#38  *  [unnamed]  5.13 28.05 180 bottom
NOREF#39  -  [#2]  112.77 175.09 270 bottom
NOREF#40  *  [unnamed]  178.12 250.25 180 bottom
ODD2  SKT-SATA7P-184-GP-U  [15-02070-5A61-A]  9.28 95 270 top
PC1  SC1U10V2KX-1DLGP  [C402H22]  27.25 140.45 180 top
PC2  SC22P50V2JN-4DLGP  [C402H22]  170.12 206.49 90 top
PC3  SC1U10V2KX-1DLGP  [C402H22]  28.64 137.65 180 top
PC4  SC4D7U25V5KX-DL-GP  [C805H54]  29.03 149.21 270 bottom
PC5  SCD1U50V3KX-DL-GP  [C603H35]  26.1 141.21 0 top
PC6  SCD1U16V2KX-3DLGP  [C402H22]  21.28 131.18 0 top
PC7  SCD022U25V2KX-DLGP  [C402H22]  21.28 136.77 270 top
PC8  SC100P50V2JN-3DLGP  [C402H22]  21.79 135.37 0 top
PC9  SC1KP50V2KX-1DLGP  [C402H22]  22.8 132.83 270 top
PC10  SCD022U25V2KX-DLGP  [C402H22]  28.67 135.09 0 top
PC11  SCD1U16V2KX-3DLGP  [C402H22]  27.7 133.46 0 top
PC12  SC4D7U25V5KX-DL-GP  [C805H54]  29.03 151.24 270 bottom
PC19  SCD1U50V3KX-DL-GP  [C603H35]  108.15 104 270 top
PC24  SC10U25V5KX-DL-GP  [C805H58]  114.24 91.43 270 bottom
PC33  SCD1U50V3KX-DL-GP  [C603H35]  13.53 191.63 0 top
PC34  SC1U10V2KX-1DLGP  [C402H22]  7.18 188.33 270 top
PC35  SC4D7U25V5KX-DL-GP  [C805H54]  15.44 193.03 0 top
PC36  SC1KP50V2KX-1DLGP  [C402H22]  18.92 193.36 270 top
PC37  SCD1U50V3KX-DL-GP  [C603H35]  13.53 210.43 0 top
PC38  SC4D7U25V5KX-DL-GP  [C805H54]  15.44 211.82 0 top
PC39  SC1U10V2KX-1DLGP  [C402H22]  7.18 205.35 270 top
PC40  SC1KP50V2KX-1DLGP  [C402H22]  18.81 209.97 270 top
PC41  SCD1U25V3KX-DLGP  [C603H36]  17.85 234.56 270 top
PC42  SC4D7U25V5KX-DL-GP  [C805H54]  15.31 227.19 180 bottom
PC43  SC1U10V2KX-1DLGP  [C402H22]  11.25 235.83 0 top
PC44  SC1KP50V2KX-1DLGP  [C402H22]  18.97 225.69 270 top
PC45  SCD1U50V3KX-DL-GP  [C603H35]  70.43 259.96 0 top
PC46  SC4D7U25V5KX-DL-GP  [C805H54]  76.9 262.24 270 top
PC47  SC1U10V2KX-1DLGP  [C402H22]  64.33 262.11 270 top
PC48  SC1KP50V2KX-1DLGP  [C402H22]  70.94 258.18 270 top
PC49  SCD1U50V3KX-DL-GP  [C603H35]  92.27 264.15 90 top
PC50  SC4D7U25V5KX-DL-GP  [C805H54]  103.83 264.02 270 top
PC51  SC1U10V2KX-1DLGP  [C402H22]  93.29 256.78 0 top
PC52  SC1KP50V2KX-1DLGP  [C402H22]  104.46 261.99 180 top
PC56  SCD1U16V2KX-3DLGP  [C402H22]  36.01 103.36 0 top
PC61  SC4D7U25V5KX-DL-GP  [C805H54]  20.14 178.04 0 top
PC62  SCD1U50V3KX-DL-GP  [C603H35]  20.44 172.99 0 top
PC63  SC1U10V2KX-1DLGP  [C402H22]  21.51 172.33 180 top
PC64  SC1KP50V2KX-1DLGP  [C402H22]  19.7 163.59 0 top
PC65  SC1KP50V2KX-1DLGP  [C402H22]  22.42 177.91 180 bottom
PC66  SCD1U16V2KX-3DLGP  [C402H22]  44.27 181.72 90 top
PC67  SC18P50V2JN-1DLGP  [C402H22]  22.8 161.35 270 top
PC68  SCD01U50V2KX-1DLGP  [C402H22]  35.76 79.11 0 top
PC69  SC4D7U25V5KX-DL-GP  [C805H54]  33.98 79.23 0 top
PC70  SCD1U50V3KX-DL-GP  [C603H35]  31.57 80.5 270 bottom
PC71  SC4D7U25V5KX-DL-GP  [C805H54]  37.64 68.34 180 top
PC72  SCD01U50V2KX-1DLGP  [C402H22]  39.06 68.06 180 top
PC73  SC1U10V2KX-1DLGP  [C402H22]  33.34 74.79 0 top
PC74  SCD1U50V3KX-DL-GP  [C603H35]  29.53 81.27 180 bottom
PC75  SCD1U50V3KX-DL-GP  [C603H35]  30.93 70.47 180 bottom
PC77  SC4D7U6D3V3KX-DLGP  [C603H36]  33.47 73.27 90 bottom
PC78  SC1U10V2KX-1DLGP  [C402H22]  69.67 67.55 180 top
PC79  SC22P50V2JN-4DLGP  [C402H22]  25.09 77.33 270 top
PC80  SC1500P50V3KX-DLGP  [C603H36]  41.22 69.96 90 bottom
PC81  SC1U16V3KX-4DLGP  [C603H36]  28.39 74.15 90 top
PC82  SC1500P50V3KX-DLGP  [C603H36]  37.79 78.98 90 bottom
PC83  SC22P50V2JN-4DLGP  [C402H22]  25.11 75.3 90 top
PC84  SC18P50V2JN-1DLGP  [C402H22]  25.16 73.34 90 bottom
PC85  SC18P50V2JN-1DLGP  [C402H22]  25.19 76.44 90 bottom
PC86  SC1U10V2KX-1DLGP  [C402H22]  163.65 213.98 180 bottom
PC87  SC1KP50V2KX-1DLGP  [C402H22]  162.76 214.87 0 bottom
PC88  SCD1U50V3KX-DL-GP  [C603H35]  156.91 217.03 180 bottom
PC89  SC10U25V6KX-4DL-GP  [C1206H71]  155.01 217.03 0 top
PC90  SC10U25V6KX-4DL-GP  [C1206H71]  166.31 210.78 0 bottom
PC91  SC10U25V6KX-4DL-GP  [C1206H71]  155.01 217.03 180 bottom
PC92  SC1U10V2KX-1DLGP  [C402H22]  162.12 209.41 270 top
PC93  SCD1U50V3KX-DL-GP  [C603H35]  165.63 220.43 180 bottom
PC94  SC10U10V5KX-2DLGP  [C805H50]  170.76 221.47 270 bottom
PC95  SC1U16V3KX-4DLGP  [C603H36]  128.47 225.41 270 top
PC96  SC18P50V2JN-1DLGP  [C402H22]  171.39 211.19 180 bottom
PC97  SC1500P50V3KX-DLGP  [C603H36]  152.47 216.14 270 bottom
PC98  SCD047U25V3KX-DLGP  [C603H36]  172.41 214.36 180 bottom
PC99  SC10U10V5KX-2DLGP  [C805H50]  174.69 218.68 0 bottom
PC100  SC10U10V5KX-2DLGP  [C805H50]  172.66 218.68 0 bottom
PC101  SC4D7U25V5KX-DL-GP  [C805H54]  166.19 124.83 270 bottom
PC102  SC4D7U25V5KX-DL-GP  [C805H54]  166.19 124.83 90 top
PC103  SCD1U50V3KX-DL-GP  [C603H35]  159.58 124.22 270 bottom
PC104  SC1U10V2KX-1DLGP  [C402H22]  159.33 125.34 270 bottom
PC105  SC1KP50V2KX-1DLGP  [C402H22]  149.68 124.12 270 top
PC106  SC1KP50V2KX-1DLGP  [C402H22]  166.44 117.84 0 bottom
PC107  SCD1U16V2KX-3DLGP  [C402H22]  171.9 100.57 90 top
PC108  SC18P50V2JN-1DLGP  [C402H22]  149.68 125.21 90 top
PC117  SC4D7U25V5KX-DL-GP  [C805H54]  18.1 178.04 0 top
PC152  SC1U25V3KX-1-DLGP  [C603H36]  111.07 129.91 90 top
PC154  SCD1U16V2KX-3DLGP  [C402H22]  110.66 132.29 90 top
PC155  SC10U10V5KX-2DLGP  [C805H50]  108.4 125.59 270 top
PC156  SC10U10V5KX-2DLGP  [C805H50]  96.59 126.22 0 top
PC157  SC100P50V2JN-3GP  [C402H22]  101.29 129.53 180 top
PC158  SC10U10V5KX-2DLGP  [C805H50]  98.62 126.22 0 top
PC159  SC10U10V5KX-6-GP  [C805H56]  100.65 126.22 0 top
PC163  SC4D7U25V5KX-DL-GP  [C805H54]  34.05 79.23 180 bottom
PC4401  SCD1U10V2KX-5DLGP  [C402H22]  42.11 253.1 0 bottom
PC4402  SCD1U10V2KX-5DLGP  [C402H22]  36.77 255.51 180 top
PC4403  SC470P50V2KX-3DLGP  [C402H22]  32.33 249.92 180 bottom
PC4404  SC2200P50V2KX-2DLGP  [C402H22]  32.84 248.4 90 bottom
PC4405  SC47P50V2JN-5DLGP  [C402H22]  35.5 247.89 0 bottom
PC4406  SC1KP50V2KX-1DLGP  [C402H22]  32.96 252.46 90 bottom
PC4407  SC1200P50V2KX-1DLGP  [C402H22]  35.5 251.95 0 bottom
PC4408  SC470P50V2KX-3DLGP  [C402H22]  36.26 254.49 90 bottom
PC4409  SC470P50V2KX-3DLGP  [C402H22]  51.12 247.89 0 bottom
PC4410  SC2200P50V2KX-2DLGP  [C402H22]  54.17 247.26 0 bottom
PC4411  SC47P50V2JN-5DLGP  [C402H22]  52.65 246.75 90 bottom
PC4412  SC1KP50V2KX-1DLGP  [C402H22]  50.49 251.57 270 bottom
PC4413  SC1200P50V2KX-1DLGP  [C402H22]  48.2 250.3 90 bottom
PC4414  SC470P50V2KX-3DLGP  [C402H22]  52.27 253.35 90 top
PC4415  SCD1U16V2KX-3DLGP  [C402H22]  39.95 239.64 270 bottom
PC4416  SCD1U16V2KX-3DLGP  [C402H22]  46.68 252.59 0 bottom
PC4417  SC1KP50V2KX-1DLGP  [C402H22]  48.58 243.06 90 bottom
PC4418  SC100P50V2JN-3DLGP  [C402H22]  51.38 244.59 180 bottom
PC4419  SC1500P50V2KX-2-DL-GP  [C402H22]  50.36 244.59 180 bottom
PC4420  SCD1U16V2KX-3DLGP  [C402H22]  36.26 242.94 180 bottom
PC4421  SCD1U16V2KX-3DLGP  [C402H22]  48.2 241.67 180 bottom
PC4422  SCD1U16V2KX-3DLGP  [C402H22]  48.2 239.64 180 bottom
PC4423  SC1KP50V2KX-1DLGP  [C402H22]  35.76 244.33 90 bottom
PC4424  SC82P50V3JN-DLGP  [C603H36]  33.09 246.49 180 bottom
PC4425  SC1500P50V2KX-2-DL-GP  [C402H22]  31.95 246.37 180 bottom
PC4426  SCD1U16V2KX-3DLGP  [C402H22]  36.26 241.03 180 bottom
PC4427  SCD1U16V2KX-3DLGP  [C402H22]  38.04 239.76 270 bottom
PC4428  SC1U10V2KX-1DLGP  [C402H22]  38.3 255.13 270 top
PC4429  SCD01U50V2KX-1DLGP  [C402H22]  44.65 252.59 0 bottom
PC4430  SC2D2U10V3KX-1DLGP-U  [C603H36]  42.11 255.36 90 bottom
PC4431  SC1KP50V2KX-1DLGP  [C402H22]  17.6 166.48 270 top
PC4432  SC1U25V5KX-3-GP  [C805H58]  76.4 38.21 90 bottom
PC4701  SCD1U10V2KX-4DLGP  [C402H22]  21.02 137.65 90 top
PC5232  SCD01U50V2KX-1DLGP  [C402H22]  71.44 39.74 90 bottom
PC5233  SCD1U50V3KX-DL-GP  [C603H35]  78.22 40.63 0 top
PC5234  SCD1U50V3KX-DL-GP  [C603H35]  78.22 43.42 180 top
PC5235  SCD1U50V3KX-DL-GP  [C603H35]  77.06 42.02 0 top
PC5236  SCD1U50V3KX-DL-GP  [C603H35]  78.05 37.45 270 top
PC5237  SC1U10V2KX-1DLGP  [C402H22]  75.3 33.62 90 top
PC5245  SC220P50V2KX-3DLGP  [C402H22]  70.17 40.56 180 top
PC5246  SC1500P50V3KX-DLGP  [C603H36]  114.86 94.59 0 top
PC5253  SC10U25V5KX-DL-GP  [C805H58]  114.24 89.39 270 bottom
PC5254  SC10U25V5KX-DL-GP  [C805H58]  114.24 89.9 90 top
PC5301  SC10U25V5KX-DL-GP  [C805H58]  6.29 107 270 top
PC5302  SC10U25V5KX-DL-GP  [C805H58]  6.29 109.03 270 top
PC5303  SC1U10V2KX-1DLGP  [C402H22]  17.34 109.59 90 bottom
PC5304  SC10U25V5KX-DL-GP  [C805H58]  10.61 137.65 270 bottom
PC5305  SC10U25V5KX-DL-GP  [C805H58]  10.61 135.62 270 bottom
PC5306  SC10U25V5KX-DL-GP  [C805H58]  10.66 131.58 270 bottom
PC5307  SCD1U50V3KX-DL-GP  [C603H35]  15.56 118.22 0 bottom
PC5308  SC10U25V5KX-DL-GP  [C805H58]  10.66 133.62 270 bottom
PC5309  SC1500P50V3KX-DLGP  [C603H36]  17.72 131.3 90 bottom
PC5310  SC68P50V2JN-1DLGP  [C402H22]  7.94 115.43 270 bottom
PC5311  SC1U10V2KX-1DLGP  [C402H22]  7.82 118.73 90 bottom
PC5312  SC1U10V2KX-1DLGP  [C402H22]  15.18 104.51 90 bottom
PC8301  SC5600P50V3KX-DL-GP  [C603H36]  97.78 108.32 180 top
PC8302  SC4D7U6D3V3KX-DLGP  [C603H36]  105.2 99.53 270 bottom
PC8303  SC22P50V2JN-4DLGP  [C402H22]  98.01 100.27 90 top
PC8306  SC22U6D3V5MX-2DLGP  [C805H54]  103.83 115.05 180 top
PC8307  SCD1U16V2KX-3DLGP  [C402H22]  102.43 94.73 0 top
PC8308  SC1U25V3KX-1-DLGP  [C603H36]  103.32 96.13 180 bottom
PC8309  SC100P50V2JN-3DLGP  [C402H22]  97 102.73 270 top
PC8311  SC1KP50V2KX-1DLGP  [C402H22]  101.29 106.21 180 top
PC8312  SC47P50V2JN-5DLGP  [C402H22]  97.86 102.98 0 bottom
PC8314  SCD1U16V2KX-3DLGP  [C402H22]  98.88 105.4 0 bottom
PC8315  SCD01U25V2KX-L1-GP  [C402H22]  100.4 105.27 90 bottom
PC8317  SC2700P50V2KX-1-DL-GP  [C402H22]  98.67 105.4 180 top
PC8501  SC1U10V2KX-1DLGP  [C402H22]  102.23 106.01 180 top
PC8607  SC22U6D3V5MX-2DLGP  [C805H54]  40.84 91.05 270 top
PC8608  SCD1U50V3KX-DL-GP  [C603H35]  46.3 109.46 0 top
PC8609  SC10U25V5KX-DL-GP  [C805H58]  42.46 112.53 90 top
PC8610  SC1500P50V3KX-DLGP  [C603H36]  38.32 94.47 0 top
PC8611  SC22U6D3V5MX-2DLGP  [C805H54]  40.84 89.01 270 top
PC8612  SC10U25V5KX-DL-GP  [C805H58]  42.46 110.5 90 top
PC8613  SCD1U50V3KX-DL-GP  [C603H35]  42.36 108.83 90 top
PC8614  SC27P50V2JN-2DLGP  [C402H22]  38.68 102.48 90 top
PC8615  SC1U25V3KX-1-DLGP  [C603H36]  44.39 108.83 270 bottom
PC8616  SC22U6D3V5MX-2DLGP  [C805H54]  40.84 86.98 270 top
PC8617  SCD1U25V2KX-1-DL-GP  [C402H22]  39.82 108.14 180 top
PC8618  SC22U6D3V5MX-2DLGP  [C805H54]  40.84 84.95 270 top
PC12172  SCD1U16V2KX-3DLGP  [C402H22]  29.53 32.88 180 bottom
PC12173  SC1U10V2KX-1DLGP  [C402H22]  58.87 81.14 180 top
PC12174  SCD1U16V2KX-3DLGP  [C402H22]  38.93 108.14 180 top
PC12175  SCD1U16V2KX-3DLGP  [C402H22]  5.56 248.78 0 bottom
PC12176  SCD1U16V2KX-3DLGP  [C402H22]  6.55 162.42 270 bottom
PC12177  SCD1U16V2KX-3DLGP  [C402H22]  16.33 146.8 270 bottom
PC12178  SCD1U16V2KX-3DLGP  [C402H22]  5.53 155.56 0 top
PC12179  SCD1U16V2KX-3DLGP  [C402H22]  5.53 139.1 270 top
PC12180  SCD1U16V2KX-3DLGP  [C402H22]  38.93 57.39 270 top
PC12181  SCD1U16V2KX-3DLGP  [C402H22]  133.8 103.24 180 bottom
PC12182  SCD1U16V2KX-3DLGP  [C402H22]  125.8 256.91 0 top
PC12183  SCD1U16V2KX-3DLGP  [C402H22]  106.75 89.14 90 bottom
PC12184  SCD1U16V2KX-3DLGP  [C402H22]  111.32 79.36 90 top
PC12185  SCD1U16V2KX-3DLGP  [C402H22]  109.06 20.13 270 bottom
PC12186  SCD1U16V2KX-3DLGP  [C402H22]  163.01 222.74 90 top
PC12187  SCD1U16V2KX-3DLGP  [C402H22]  153.61 223.63 180 top
PD4401  RB520SM-30T2R-GP  [D1608-035030AKH28]  77.82 33.74 90 top
PD5301  SSM54PT-GP  [D5226145AKH91]  13.91 126.99 180 bottom
PD8301  1SS355GP-GP  [SOD323AKH40]  102.94 106.67 180 bottom
PG1  COPPER-CLOSE-GP-U  [CON2C-U]  29.03 194.42 90 top
PG2  COPPER-CLOSE-GP-U  [CON2C-U]  34.61 194.42 270 top
PG3  COPPER-CLOSE-GP-U  [CON2C-U]  29.03 210.43 90 top
PG4  COPPER-CLOSE-GP-U  [CON2C-U]  34.61 210.43 270 top
PG5  COPPER-CLOSE-GP-U  [CON2C-U]  29.03 223.76 90 top
PG6  COPPER-CLOSE-GP-U  [CON2C-U]  34.61 223.76 270 top
PG7  COPPER-CLOSE-GP-U  [CON2C-U]  74.75 247.51 90 top
PG8  COPPER-CLOSE-GP-U  [CON2C-U]  80.33 247.51 270 top
PG9  COPPER-CLOSE-GP-U  [CON2C-U]  103.07 250.05 0 top
PG10  COPPER-CLOSE-GP-U  [CON2C-U]  103.07 244.46 180 top
PG11  COPPER-CLOSE-GP-U  [CON2C-U]  29.66 165.98 90 top
PG12  COPPER-CLOSE-GP-U  [CON2C-U]  35.25 165.98 270 top
PG13  GAP-CLOSE-PWR-3-GP  [GAP-CLOSE-PWR-3]  33.09 74.41 0 bottom
PG14  GAP-CLOSE-PWR-3-GP  [GAP-CLOSE-PWR-3]  59.86 81.24 270 top
PG15  GAP-CLOSE-PWR-3-GP  [GAP-CLOSE-PWR-3]  74.75 61.07 0 top
PG16  GAP-CLOSE-PWR-3-GP  [GAP-CLOSE-PWR-3]  33.47 72.12 0 bottom
PG17  GAP-CLOSE-PWR-3-GP  [GAP-CLOSE-PWR-3]  153.76 98.69 0 top
PG4905  GAP-CLOSE-PWR-3-GP  [GAP-CLOSE-PWR-3]  80.38 44.32 180 top
PG4907  GAP-CLOSE-PWR-3-GP  [GAP-CLOSE-PWR-3]  80.38 42.66 180 top
PL1  IND-D36UH-19-GP  [L115100-2H158]  31.82 194.42 90 top
PL2  IND-D36UH-19-GP  [L115100-2H158]  31.82 210.43 90 top
PL3  IND-D36UH-19-GP  [L115100-2H158]  31.82 223.76 90 top
PL4  IND-D36UH-19-GP  [L115100-2H158]  77.54 247.51 90 top
PL5  IND-D36UH-19-GP  [L115100-2H158]  103.07 247.26 0 top
PL6  IND-D36UH-19-GP  [L115100-2H158]  32.45 165.98 90 top
PL7  IND-1D5UH-53-GP  [L686647H119]  30.93 177.53 0 top
PL8  IND-3D3UH-116-GP  [L686647H119]  46.17 79.36 180 top
PL9  IND-1D5UH-52-GP  [L115100-2030H158]  54.55 68.69 90 top
PL10  IND-D68UH-58-GP  [L112100-2030H158]  138.75 216.39 270 top
PL11  IND-D68UH-58-GP  [L112100-2030H158]  167.96 108.44 0 top
PL12  IND-D36UH-19-GP  [L115100-2H158]  118.43 109.59 180 top
PL5301  IND-5D6UH-45-GP  [L686647H119]  8.2 126.1 90 bottom
PL8602  IND-1UH-94-GP  [L686647H119]  43 96.51 270 top
PQ4408  2N7002K-2-GP  [SOT23DGS2D4H44]  74.87 45.2 270 top
PQ5006  2N7002KDW-GP  [SOT-363H44]  68.9 44.31 90 top
PQ5007  NTJD512NT1G-GP  [SOT-363H44]  47.9 44.61 90 bottom
PQ5301  2N7002A-7-GP  [SOT23DGS2D4H48]  18.48 107.3 270 bottom
PQ5302  2N7002A-7-GP  [SOT23DGS2D4H48]  14.67 107.17 180 bottom
PR1  1KR2J-1-GP  [R402H16]  36.19 142.23 0 top
PR2  2D2R5J-1-GP  [R805H24]  30.85 141.95 0 top
PR3  -  [0R0805-PAD]  21.28 147.69 270 top
PR4  10KR2J-3-GP  [R402H16]  21.02 138.67 90 top
PR5  -  [0R0805-PAD]  21.28 145.66 270 top
PR6  -  [0R0805-PAD]  21.28 149.72 270 top
PR7  10KR2J-3-GP  [R402H16]  76.52 46.47 270 bottom
PR8  2D2R5J-1-GP  [R805H24]  28.82 141.95 0 top
PR9  49K9R2F-L-GP  [R402H16]  34.21 137.2 90 top
PR10  24K9R2F-L-GP  [R402H16]  30.5 136.56 270 top
PR11  6K98R2F-GP  [R402H16]  20.77 135.37 0 top
PR12  0R0402-PAD-2-GP  [0R0402-PAD-1]  24.33 132.83 180 top
PR13  93K1R2F-L-GP  [R402H16]  29.69 135.09 0 top
PR14  9K53R2F-GP  [R402H16]  21.53 133.84 270 top
PR15  3KR2F-GP  [R402H16]  24.33 130.8 0 top
PR16  100R2F-L1-GP-U  [R402H14]  22.8 130.67 90 top
PR17  100R2F-L1-GP-U  [R402H14]  22.8 131.81 90 top
PR18  100R2F-L1-GP-U  [R402H14]  25.6 132.83 0 top
PR19  0R5J-5-GP  [R805H24]  24.45 141.21 180 top
PR20  2D2R5J-1-GP  [R805H24]  23.31 158.23 0 bottom
PR43  2D2R5J-1-GP  [R805H24]  107.51 106.54 90 top
PR60  NTC-100K-12-GP-U  [NTC-402H22-U]  106.47 94.58 180 top
PR74  2D2R5J-1-GP  [R805H24]  8.96 186.8 270 top
PR75  -  [0R0805-PAD]  6.8 199.25 90 top
PR76  -  [0R0805-PAD]  6.8 197.22 90 top
PR77  2D2R5J-1-GP  [R805H24]  11.12 192.8 270 top
PR78  -  [0R0805-PAD]  6.8 195.19 90 top
PR79  2D2R5J-1-GP  [R805H24]  22.29 194.04 270 bottom
PR80  10KR2J-3-GP  [R402H16]  25.9 200.57 90 top
PR81  51R2J-2-GP  [R402H16]  6.93 190.99 180 top
PR82  2D2R6J-3-GP  [R1206H28]  22.27 193.89 270 top
PR83  2D2R5J-1-GP  [R805H24]  9.98 205.6 270 top
PR84  2D2R5J-1-GP  [R805H24]  10.99 211.7 270 top
PR85  2D2R5J-1-GP  [R805H24]  22.29 210.55 270 bottom
PR86  10KR2J-3-GP  [R402H16]  25.85 216.78 90 top
PR87  51R2J-2-GP  [R402H16]  7.05 209.92 180 top
PR88  2D2R6J-3-GP  [R1206H28]  22.17 210.43 270 top
PR89  2D2R5J-1-GP  [R805H24]  9.72 235.44 180 top
PR90  2D2R5J-1-GP  [R805H24]  16.83 236.21 270 top
PR91  2D2R5J-1-GP  [R805H24]  22.29 235.06 90 top
PR92  10KR2J-3-GP  [R402H16]  25.85 232.52 90 top
PR93  51R2J-2-GP  [R402H16]  12.64 238.87 90 top
PR94  2D2R6J-3-GP  [R1206H28]  22.29 226.17 270 top
PR95  2D2R5J-1-GP  [R805H24]  70.68 262.62 270 top
PR96  -  [0R0805-PAD]  85.79 263 180 top
PR97  -  [0R0805-PAD]  83.76 263 180 top
PR98  2D2R5J-1-GP  [R805H24]  64.33 259.83 180 top
PR99  -  [0R0805-PAD]  81.73 263 180 top
PR100  -  [0R0805-PAD]  79.7 263 180 top
PR101  10KR2J-3-GP  [R402H16]  72.21 254.11 180 bottom
PR102  51R2J-2-GP  [R402H16]  62.93 263.13 270 top
PR103  2D2R5J-1-GP  [R805H24]  81.35 254.37 90 bottom
PR104  2D2R6J-3-GP  [R1206H28]  71.7 255.38 180 top
PR105  2D2R5J-1-GP  [R805H24]  89.86 261.35 0 top
PR106  2D2R5J-1-GP  [R805H24]  94.81 256.65 180 top
PR107  2D2R5J-1-GP  [R805H24]  110.23 251.47 180 top
PR108  10KR2J-3-GP  [R402H16]  104.34 255.38 180 bottom
PR109  51R2J-2-GP  [R402H16]  90.75 257.16 270 top
PR110  2D2R6J-3-GP  [R1206H28]  103.83 258.69 180 top
PR114  2D2R5J-1-GP  [R805H24]  114.88 98.79 180 top
PR123  10KR2J-3-GP  [R402H16]  29.28 128.89 90 top
PR133  -  [0R0805-PAD]  15.41 184.01 270 top
PR134  -  [0R0805-PAD]  15.41 181.98 270 top
PR135  10KR2J-3-GP  [R402H16]  17.6 167.5 90 top
PR136  75KR2F-GP  [R402H16]  16.58 163.82 0 top
PR137  -  [0R0805-PAD]  45.03 176.26 90 bottom
PR138  -  [0R0805-PAD]  45.03 178.29 90 bottom
PR139  2D2R3-1-U-GP  [R603H22]  19.27 172.99 180 top
PR140  -  [0R0805-PAD]  45.03 180.33 90 bottom
PR141  -  [0R0805-PAD]  45.03 178.29 270 top
PR142  -  [0R0805-PAD]  45.03 180.33 270 top
PR143  470KR2F-GP  [R402H16]  23.36 168.11 180 top
PR144  -  [0R0805-PAD]  45.03 176.26 270 top
PR145  2D2R5J-1-GP  [R805H24]  24.71 178.8 90 bottom
PR146  11K8R2F-GP  [R402H16]  22.8 162.37 270 top
PR147  33KR2F-GP  [R402H16]  21.79 163.44 90 top
PR148  -  [0R0805-PAD]  26.49 69.68 90 top
PR149  -  [0R0805-PAD]  26.49 71.61 90 top
PR152  100KR2J-1-GP  [R402H16]  32.38 76.92 180 bottom
PR153  2D2R5J-1-GP  [R805H24]  27.83 81.67 180 bottom
PR154  2D2R5J-1-GP  [R805H24]  28.42 69.96 270 bottom
PR155  -  [0R0805-PAD]  39.57 83.17 90 bottom
PR156  -  [0R0805-PAD]  46.42 64.5 0 bottom
PR157  2D2R5J-1-GP  [R805H24]  40.96 78.98 90 bottom
PR158  6K65R2F-GP  [R402H16]  25.09 78.35 90 top
PR159  15KR2F-GP  [R402H16]  25.11 74.28 270 top
PR160  2D2R5J-1-GP  [R805H24]  45.03 69.96 90 bottom
PR161  10KR2F-2-GP  [R402H16]  26.61 77.84 180 top
PR162  100KR2J-1-GP  [R402H16]  24.66 79.84 180 bottom
PR163  56KR2F-GP  [R402H16]  33.09 75.42 90 bottom
PR164  10KR2F-2-GP  [R402H16]  25.11 76.31 270 top
PR165  68KR2F-GP  [R402H16]  24.76 74.97 0 bottom
PR166  100KR2F-L1-GP  [R402H16]  36.39 75.07 180 bottom
PR167  -  [0R0805-PAD]  74.75 59.55 90 bottom
PR168  56K2R2F-2-GP  [R402H16]  25.16 72.33 90 bottom
PR169  62KR2F-GP  [R402H16]  24.28 77.41 90 bottom
PR170  -  [0R0805-PAD]  74.75 57.52 90 bottom
PR171  -  [0R0805-PAD]  74.75 55.49 90 bottom
PR172  -  [0R0805-PAD]  74.75 59.55 270 top
PR173  -  [0R0805-PAD]  74.75 57.52 270 top
PR174  -  [0R0805-PAD]  74.75 55.49 270 top
PR175  -  [0R0805-PAD]  61.16 79.49 270 top
PR176  -  [0R0805-PAD]  61.16 77.46 270 top
PR177  -  [0R0805-PAD]  61.16 75.42 270 top
PR178  -  [0R0805-PAD]  138.42 254.73 90 top
PR179  -  [0R0805-PAD]  138.42 256.66 90 top
PR180  -  [0R0805-PAD]  138.42 258.59 90 top
PR181  5D1R2F-GP  [R402H16]  162.38 212.2 270 top
PR182  -  [0R0805-PAD]  138.42 260.52 90 top
PR183  4K53R2F-1-GP  [R402H16]  161.74 214.87 0 bottom
PR184  -  [0R0603-PAD]  161.87 208.14 270 top
PR185  10KR2F-2-GP  [R402H16]  162.25 210.68 270 top
PR186  2D2R3-1-U-GP  [R603H22]  167.61 221.17 90 bottom
PR187  620KR2F-GP  [R402H16]  167.96 210.68 0 bottom
PR188  -  [0R0805-PAD]  167.07 222.87 270 bottom
PR189  -  [0R0805-PAD]  167.07 224.9 270 bottom
PR190  2D2R5J-1-GP  [R805H24]  149.29 216.52 270 bottom
PR191  -  [0R0805-PAD]  173.93 210.43 0 bottom
PR192  40K2R2F-GP  [R402H16]  172.41 211.19 180 bottom
PR193  48D7KR2F-GP  [R402H16]  170.38 211.19 180 bottom
PR194  -  [0R0805-PAD]  122.45 204.78 180 bottom
PR195  -  [0R0805-PAD]  130.17 204.78 180 bottom
PR196  -  [0R0805-PAD]  173.93 214.24 0 bottom
PR197  -  [0R0805-PAD]  134.03 204.78 180 bottom
PR198  -  [0R0805-PAD]  132.1 204.78 180 bottom
PR199  -  [0R0805-PAD]  178.76 216.01 180 bottom
PR200  -  [0R0805-PAD]  124.38 204.78 180 bottom
PR201  -  [0R0805-PAD]  135.98 204.76 180 bottom
PR202  -  [0R0805-PAD]  176.73 216.01 180 bottom
PR203  -  [0R0805-PAD]  128.24 204.78 180 bottom
PR204  -  [0R0805-PAD]  126.31 204.78 180 bottom
PR205  -  [0R0805-PAD]  155.9 110.73 180 top
PR206  -  [0R0805-PAD]  153.97 110.73 180 top
PR207  10KR2J-3-GP  [R402H16]  149.68 121.91 270 bottom
PR208  33KR2F-GP  [R402H16]  149.68 122.92 90 bottom
PR209  2D2R3-1-U-GP  [R603H22]  159.58 122.95 270 bottom
PR210  470KR2F-GP  [R402H16]  149.68 124.95 90 bottom
PR211  2D2R5J-1-GP  [R805H24]  166.44 121.91 0 bottom
PR212  10KR2F-2-GP  [R402H16]  149.68 126.22 90 top
PR213  -  [0R0805-PAD]  161.36 97.4 180 top
PR214  22K6R2F-1-GP  [R402H16]  149.68 123.94 90 bottom
PR215  -  [0R0805-PAD]  159.4 97.4 180 top
PR216  -  [0R0805-PAD]  155.52 97.4 180 top
PR217  -  [0R0805-PAD]  157.45 97.4 180 top
PR218  -  [0R0805-PAD]  162.12 94.63 90 top
PR219  -  [0R0805-PAD]  162.12 92.7 90 top
PR220  -  [0R0805-PAD]  162.12 90.77 90 top
PR227  -  [0R0402-PAD]  109.92 133.34 270 top
PR228  -  [0R0805-PAD]  93.41 127.75 90 top
PR229  10KR2F-2-GP  [R402H16]  101.24 132.96 180 top
PR230  -  [0R0805-PAD]  93.41 125.82 90 top
PR231  3K16R2F-GP  [R402H16]  100.27 129.53 180 top
PR232  10KR2J-3-GP  [R402H16]  45.79 112.38 270 top
PR235  10KR2J-3-GP  [R402H16]  45.79 111.37 270 top
PR246  10KR2J-3-GP  [R402H16]  79.09 77.74 0 top
PR583  47KR2J-2-GP  [R402H16]  108.4 133.72 0 top
PR4401  47KR2J-2-GP  [R402H16]  39.06 250.05 90 top
PR4402  1KR2J-1-GP  [R402H16]  33.85 255.51 0 top
PR4403  1KR2J-1-GP  [R402H16]  45.66 252.59 180 bottom
PR4404  2D2R5J-1-GP  [R805H24]  41.73 257.03 270 bottom
PR4407  0R0402-PAD-2-GP  [0R0402-PAD-1]  32.96 251.45 90 bottom
PR4408  3K3R2F-2-GP  [R402H16]  34.49 251.95 180 bottom
PR4409  30K9R2F-GP  [R402H16]  36.26 253.48 270 bottom
PR4412  0R0402-PAD-2-GP  [0R0402-PAD-1]  50.49 250.56 270 bottom
